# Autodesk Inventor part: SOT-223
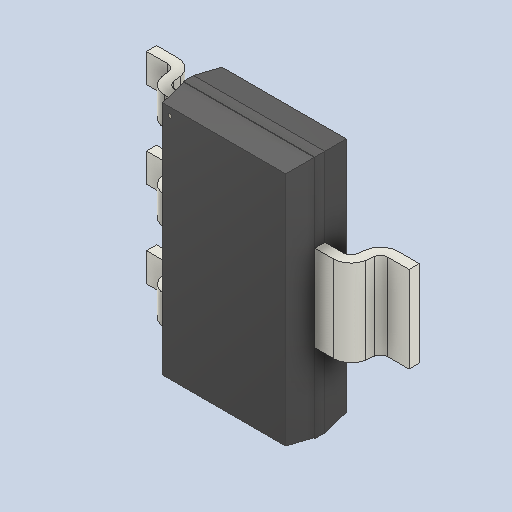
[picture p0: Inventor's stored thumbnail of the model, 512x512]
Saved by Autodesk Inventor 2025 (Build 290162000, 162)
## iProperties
Created: 2026-09
Part Number: SOT-223
Material: Generic
Document SubType Name: Modeling
Designer: Leonardo
Density: 1 g/cm^3
Appearance: Default
Author: Leonardo
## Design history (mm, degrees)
feature "Base1"
body "Solid1"
